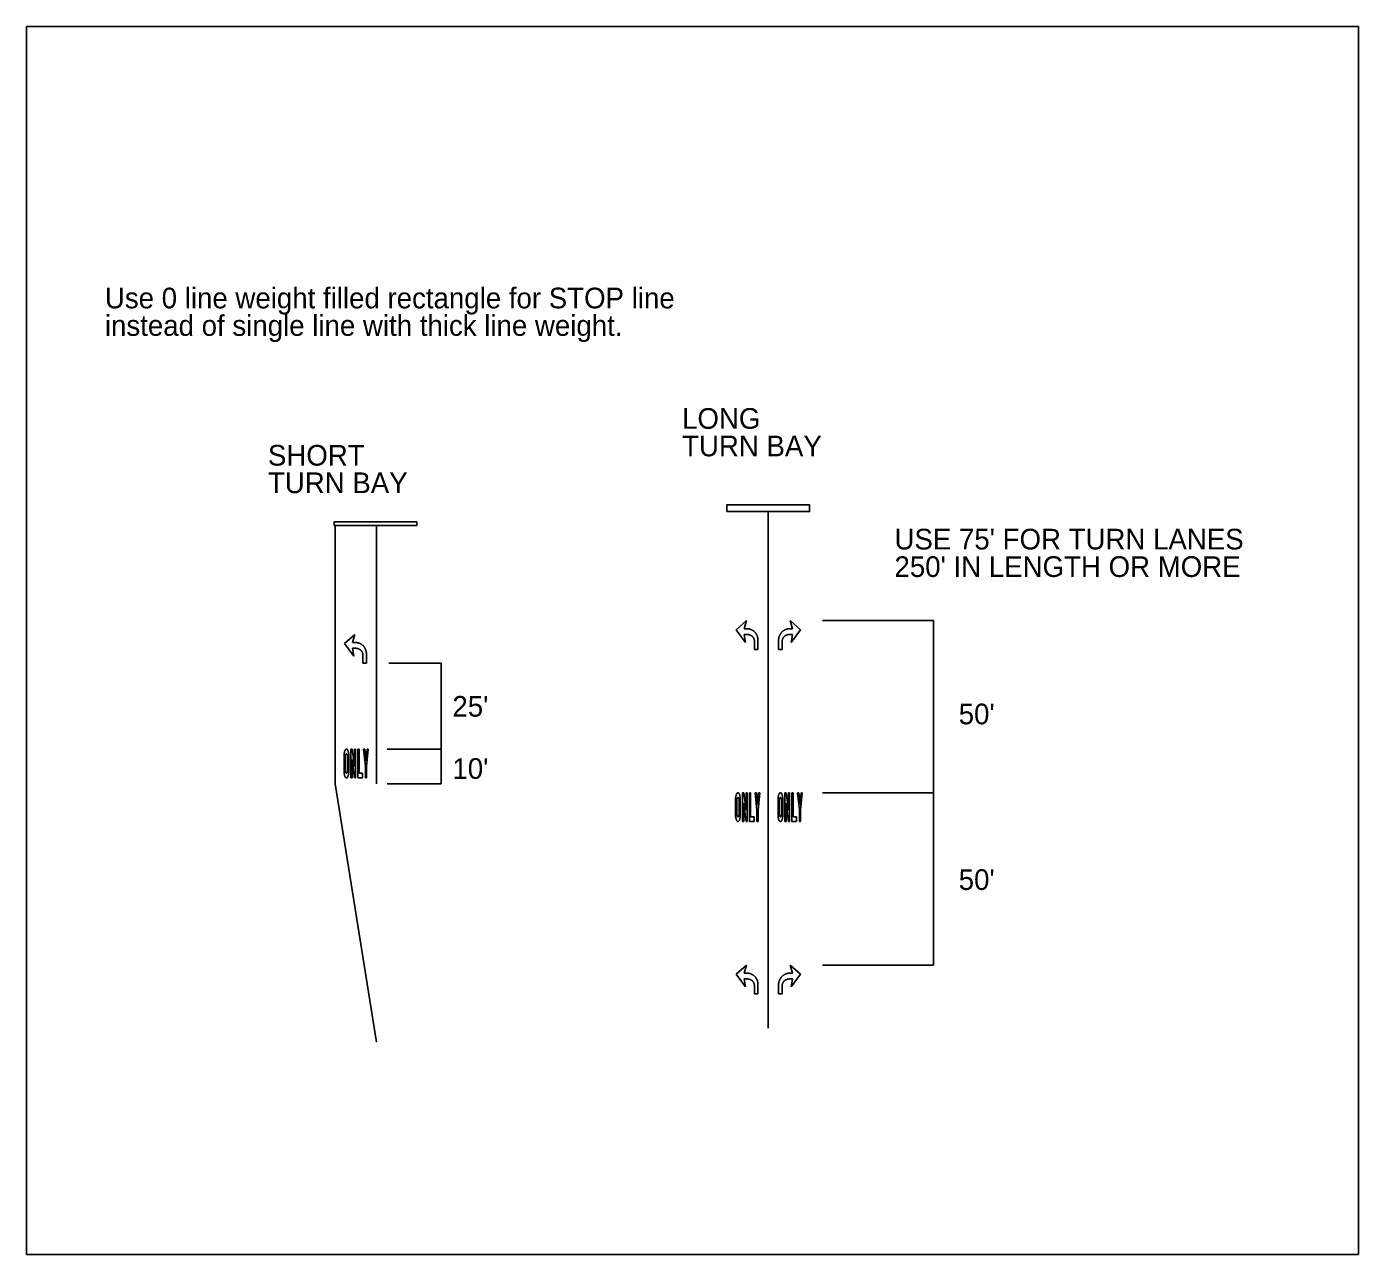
# Model space of a CAD drawing. Extents: x 979036 to 996074, y 1836928 to 1845163.
# Drawn here: x 995687.7 to 996074.4, y 1842782.4 to 1843138.9 of the extents above; entities that cross this region are included whole.
import ezdxf

# ---------------------------------------------------------------- set-up
doc = ezdxf.new("R2010")
doc.units = 0
for name, color, linetype in [('Default', 7, 'Continuous'), ('R_Striping', 7, 'Continuous'), ('STRIPE_White Stopbar', 7, 'Continuous'), ('STRIPE_White Turn Arrow', 7, 'Continuous'), ('STRIPE_White_6in', 7, 'Continuous'), ('STRIPE_White_ONLY', 7, 'Continuous')]:
    doc.layers.add(name, color=color, linetype=linetype)

msp = doc.modelspace()

# ---------------------------------------------------------------- linework, layer by layer
at = {"layer": 'Default'}
for p, q in [((995918.82, 1842966.41), (995951.06, 1842966.41)), ((995951.06, 1842966.41), (995951.06, 1842916.41)), ((995792.86, 1842954.07), (995808.11, 1842954.07)), ((995808.11, 1842954.07), (995808.11, 1842929.07)), ((995792.39, 1842929.07), (995808.11, 1842929.07)), ((995808.11, 1842929.07), (995808.11, 1842919.07)), ((995792.39, 1842919.07), (995808.11, 1842919.07)), ((995918.82, 1842916.41), (995951.06, 1842916.41)), ((995951.06, 1842916.41), (995951.06, 1842866.41)), ((995918.82, 1842866.41), (995951.06, 1842866.41))]:
    msp.add_line(p, q, dxfattribs=at)
msp.add_lwpolyline([(995687.71, 1843138.86), (996074.4, 1843138.86), (996074.4, 1842782.42), (995687.71, 1842782.42)], close=True, dxfattribs=at)
at = {"layer": 'R_Striping'}
for q in [(995777.32, 1842994.07), (995789.32, 1842844.07)]:
    msp.add_line((995777.32, 1842919.07), q, dxfattribs=at)
at = {"layer": 'STRIPE_White Stopbar'}
for points in [[(995891.07, 1842998.07), (995915.07, 1842998.07), (995915.07, 1843000.07), (995891.07, 1843000.07)], [(995776.99, 1842994.07), (995800.99, 1842994.07), (995800.99, 1842995.07), (995776.99, 1842995.07)]]:
    msp.add_lwpolyline(points, close=True, dxfattribs=at)
at = {"layer": 'STRIPE_White Turn Arrow'}
for p, q in [((995896.74, 1842966.41), (995893.74, 1842963.74)), ((995896.06, 1842964.07), (995896.74, 1842966.41)), ((995910.08, 1842964.07), (995909.4, 1842966.41)), ((995909.4, 1842966.41), (995912.4, 1842963.74)), ((995783.04, 1842962.4), (995780.04, 1842959.74)), ((995782.36, 1842960.07), (995783.04, 1842962.4)), ((995893.74, 1842963.74), (995896.4, 1842960.09)), ((995897.06, 1842964.07), (995896.06, 1842964.07)), ((995896.4, 1842960.09), (995896.06, 1842962.39)), ((995896.06, 1842962.39), (995897.07, 1842962.39)), ((995897.07, 1842962.39), (995897.26, 1842962.36)), ((995897.67, 1842963.95), (995897.47, 1842964)), ((995900.07, 1842958.07), (995900.07, 1842961.07)), ((995906.07, 1842958.07), (995906.07, 1842961.07)), ((995908.47, 1842963.95), (995908.67, 1842964)), ((995909.07, 1842962.39), (995908.89, 1842962.36)), ((995910.08, 1842962.39), (995909.07, 1842962.39)), ((995909.08, 1842964.07), (995910.08, 1842964.07)), ((995912.4, 1842963.74), (995909.74, 1842960.09)), ((995909.74, 1842960.09), (995910.08, 1842962.39)), ((995780.04, 1842959.74), (995782.7, 1842956.08)), ((995783.36, 1842960.07), (995782.36, 1842960.07)), ((995782.7, 1842956.08), (995782.36, 1842958.38)), ((995782.36, 1842958.38), (995783.37, 1842958.38)), ((995783.37, 1842958.38), (995783.56, 1842958.35)), ((995783.98, 1842959.95), (995783.77, 1842960)), ((995786.37, 1842954.07), (995786.37, 1842957.07)), ((995899.06, 1842960.38), (995899.07, 1842958.07)), ((995899.07, 1842958.07), (995900.07, 1842958.07)), ((995907.07, 1842958.07), (995906.07, 1842958.07)), ((995907.08, 1842960.38), (995907.07, 1842958.07)), ((995785.36, 1842956.38), (995785.37, 1842954.07)), ((995785.37, 1842954.07), (995786.37, 1842954.07)), ((995896.74, 1842866.41), (995893.74, 1842863.74)), ((995896.06, 1842864.07), (995896.74, 1842866.41)), ((995897.06, 1842864.07), (995896.06, 1842864.07)), ((995897.67, 1842863.95), (995897.47, 1842864)), ((995908.47, 1842863.95), (995908.67, 1842864)), ((995909.08, 1842864.07), (995910.08, 1842864.07)), ((995910.08, 1842864.07), (995909.4, 1842866.41)), ((995909.4, 1842866.41), (995912.4, 1842863.74)), ((995893.74, 1842863.74), (995896.4, 1842860.09)), ((995896.4, 1842860.09), (995896.06, 1842862.39)), ((995896.06, 1842862.39), (995897.07, 1842862.39)), ((995897.07, 1842862.39), (995897.26, 1842862.36)), ((995899.06, 1842860.38), (995899.07, 1842858.07)), ((995900.07, 1842858.07), (995900.07, 1842861.07)), ((995906.07, 1842858.07), (995906.07, 1842861.07)), ((995907.08, 1842860.38), (995907.07, 1842858.07)), ((995909.07, 1842862.39), (995908.89, 1842862.36)), ((995910.08, 1842862.39), (995909.07, 1842862.39)), ((995912.4, 1842863.74), (995909.74, 1842860.09)), ((995909.74, 1842860.09), (995910.08, 1842862.39)), ((995899.07, 1842858.07), (995900.07, 1842858.07)), ((995907.07, 1842858.07), (995906.07, 1842858.07))]:
    msp.add_line(p, q, dxfattribs=at)
for points in [[(995897.47, 1842964), (995897.27, 1842964.05), (995897.06, 1842964.07)], [(995897.26, 1842962.36), (995898.93, 1842962.06), (995899.06, 1842960.38)], [(995900.07, 1842961.07), (995899.66, 1842963.41), (995897.67, 1842963.95)], [(995906.07, 1842961.07), (995906.49, 1842963.41), (995908.47, 1842963.95)], [(995908.89, 1842962.36), (995907.21, 1842962.06), (995907.08, 1842960.38)], [(995908.67, 1842964), (995908.87, 1842964.05), (995909.08, 1842964.07)], [(995783.77, 1842960), (995783.58, 1842960.04), (995783.36, 1842960.07)], [(995783.56, 1842958.35), (995785.23, 1842958.05), (995785.36, 1842956.38)], [(995786.37, 1842957.07), (995785.96, 1842959.41), (995783.98, 1842959.95)], [(995897.47, 1842864), (995897.27, 1842864.05), (995897.06, 1842864.07)], [(995900.07, 1842861.07), (995899.66, 1842863.41), (995897.67, 1842863.95)], [(995906.07, 1842861.07), (995906.49, 1842863.41), (995908.47, 1842863.95)], [(995908.67, 1842864), (995908.87, 1842864.05), (995909.08, 1842864.07)], [(995897.26, 1842862.36), (995898.93, 1842862.06), (995899.06, 1842860.38)], [(995908.89, 1842862.36), (995907.21, 1842862.06), (995907.08, 1842860.38)]]:
    msp.add_open_spline(points, degree=2, dxfattribs=at)
at = {"layer": 'STRIPE_White_6in'}
for p, q in [((995903.07, 1842998.07), (995903.07, 1842848.07)), ((995789.32, 1842994.07), (995789.32, 1842919.07))]:
    msp.add_line(p, q, dxfattribs=at)
at = {"layer": 'STRIPE_White_ONLY'}
for p, q in [((995779.88, 1842927.74), (995779.88, 1842927.75)), ((995779.88, 1842922.09), (995779.88, 1842927.74)), ((995780.22, 1842927.08), (995780.22, 1842922.75)), ((995780.88, 1842922.75), (995780.88, 1842927.08)), ((995781.23, 1842927.76), (995781.23, 1842922.08)), ((995781.89, 1842920.74), (995781.89, 1842929.07)), ((995781.89, 1842929.07), (995782.23, 1842929.07)), ((995782.89, 1842920.74), (995782.21, 1842926.07)), ((995782.21, 1842926.07), (995782.23, 1842920.74)), ((995782.23, 1842929.07), (995782.89, 1842924.07)), ((995782.89, 1842924.07), (995782.89, 1842929.07)), ((995782.89, 1842929.07), (995783.23, 1842929.07)), ((995783.23, 1842929.07), (995783.23, 1842920.74)), ((995783.89, 1842920.74), (995783.89, 1842929.07)), ((995783.89, 1842929.07), (995784.23, 1842929.07)), ((995784.23, 1842929.07), (995784.23, 1842922.08)), ((995785.89, 1842929.07), (995785.56, 1842929.07)), ((995785.56, 1842929.07), (995786.08, 1842924.05)), ((995786.25, 1842925.73), (995785.89, 1842929.07)), ((995786.56, 1842929.07), (995786.25, 1842925.73)), ((995786.41, 1842924.07), (995786.9, 1842929.07)), ((995786.9, 1842929.07), (995786.56, 1842929.07)), ((995784.23, 1842922.08), (995785.22, 1842922.08)), ((995785.22, 1842922.08), (995785.23, 1842920.74)), ((995786.08, 1842924.05), (995786.08, 1842920.74)), ((995786.41, 1842920.74), (995786.41, 1842924.07)), ((995782.23, 1842920.74), (995781.89, 1842920.74)), ((995783.23, 1842920.74), (995782.89, 1842920.74)), ((995785.23, 1842920.74), (995783.89, 1842920.74)), ((995786.08, 1842920.74), (995786.41, 1842920.74)), ((995893.58, 1842915.08), (995893.58, 1842915.09)), ((995893.58, 1842909.42), (995893.58, 1842915.08)), ((995893.92, 1842914.42), (995893.92, 1842910.09)), ((995894.58, 1842910.09), (995894.58, 1842914.42)), ((995894.92, 1842915.09), (995894.92, 1842909.42)), ((995895.59, 1842908.07), (995895.59, 1842916.41)), ((995895.59, 1842916.41), (995895.92, 1842916.41)), ((995895.92, 1842916.41), (995896.59, 1842911.41)), ((995896.59, 1842911.41), (995896.59, 1842916.41)), ((995896.59, 1842916.41), (995896.92, 1842916.41)), ((995896.92, 1842916.41), (995896.92, 1842908.07)), ((995897.59, 1842908.07), (995897.59, 1842916.41)), ((995897.59, 1842916.41), (995897.92, 1842916.41)), ((995897.92, 1842916.41), (995897.93, 1842909.41)), ((995899.59, 1842916.41), (995899.26, 1842916.41)), ((995899.26, 1842916.41), (995899.78, 1842911.39)), ((995899.94, 1842913.07), (995899.59, 1842916.41)), ((995900.26, 1842916.41), (995899.94, 1842913.07)), ((995900.11, 1842911.4), (995900.59, 1842916.41)), ((995900.59, 1842916.41), (995900.26, 1842916.41)), ((995905.9, 1842915.08), (995905.9, 1842915.09)), ((995905.9, 1842909.42), (995905.9, 1842915.08)), ((995906.24, 1842914.42), (995906.24, 1842910.09)), ((995906.9, 1842910.09), (995906.9, 1842914.42)), ((995907.25, 1842915.09), (995907.25, 1842909.42)), ((995907.91, 1842908.07), (995907.91, 1842916.41)), ((995907.91, 1842916.41), (995908.25, 1842916.41)), ((995908.25, 1842916.41), (995908.91, 1842911.41)), ((995908.91, 1842911.41), (995908.91, 1842916.41)), ((995908.91, 1842916.41), (995909.25, 1842916.41)), ((995909.25, 1842916.41), (995909.25, 1842908.07)), ((995909.91, 1842908.07), (995909.91, 1842916.41)), ((995909.91, 1842916.41), (995910.25, 1842916.41)), ((995910.25, 1842916.41), (995910.25, 1842909.41)), ((995911.92, 1842916.41), (995911.58, 1842916.41)), ((995911.58, 1842916.41), (995912.1, 1842911.39)), ((995912.27, 1842913.07), (995911.92, 1842916.41)), ((995912.58, 1842916.41), (995912.27, 1842913.07)), ((995912.43, 1842911.4), (995912.92, 1842916.41)), ((995912.92, 1842916.41), (995912.58, 1842916.41)), ((995896.59, 1842908.07), (995895.9, 1842913.41)), ((995895.9, 1842913.41), (995895.92, 1842908.07)), ((995899.78, 1842911.39), (995899.78, 1842908.07)), ((995900.11, 1842908.07), (995900.11, 1842911.4)), ((995908.91, 1842908.07), (995908.23, 1842913.41)), ((995908.23, 1842913.41), (995908.25, 1842908.07)), ((995912.1, 1842911.39), (995912.1, 1842908.07)), ((995912.43, 1842908.07), (995912.43, 1842911.4)), ((995895.92, 1842908.07), (995895.59, 1842908.07)), ((995896.92, 1842908.07), (995896.59, 1842908.07)), ((995898.92, 1842908.07), (995897.59, 1842908.07)), ((995897.93, 1842909.41), (995898.92, 1842909.41)), ((995898.92, 1842909.41), (995898.92, 1842908.07)), ((995899.78, 1842908.07), (995900.11, 1842908.07)), ((995908.25, 1842908.07), (995907.91, 1842908.07)), ((995909.25, 1842908.07), (995908.91, 1842908.07)), ((995911.25, 1842908.07), (995909.91, 1842908.07)), ((995910.25, 1842909.41), (995911.25, 1842909.41)), ((995911.25, 1842909.41), (995911.25, 1842908.07)), ((995912.1, 1842908.07), (995912.43, 1842908.07))]:
    msp.add_line(p, q, dxfattribs=at)
for centre, start, end in [((995780.56, 1842928.85), 62.2844, 117.7155), ((995780.56, 1842920.98), 242.2844, 306.378), ((995894.26, 1842916.19), 62.2844, 117.7155), ((995906.58, 1842916.19), 62.2844, 117.7155), ((995894.26, 1842908.32), 242.2844, 306.378), ((995906.58, 1842908.32), 242.2844, 306.378)]:
    msp.add_arc(centre, 0.261, start, end, dxfattribs=at)
for points in [[(995779.88, 1842927.75), (995780.1, 1842928.9), (995780.44, 1842929.08)], [(995780.55, 1842927.76), (995780.38, 1842927.74), (995780.22, 1842927.08)], [(995780.88, 1842927.08), (995780.73, 1842927.74), (995780.55, 1842927.76)], [(995780.68, 1842929.08), (995781.02, 1842928.9), (995781.23, 1842927.76)], [(995780.44, 1842920.75), (995780.1, 1842920.94), (995779.88, 1842922.09)], [(995780.22, 1842922.75), (995780.38, 1842922.1), (995780.55, 1842922.08)], [(995780.55, 1842922.08), (995780.72, 1842922.09), (995780.88, 1842922.75)], [(995781.23, 1842922.08), (995781.03, 1842920.99), (995780.72, 1842920.77)], [(995893.58, 1842915.09), (995893.8, 1842916.24), (995894.14, 1842916.42)], [(995894.25, 1842915.09), (995894.08, 1842915.08), (995893.92, 1842914.42)], [(995894.58, 1842914.42), (995894.42, 1842915.08), (995894.25, 1842915.09)], [(995894.38, 1842916.42), (995894.72, 1842916.24), (995894.92, 1842915.09)], [(995905.9, 1842915.09), (995906.12, 1842916.24), (995906.46, 1842916.42)], [(995906.57, 1842915.09), (995906.4, 1842915.08), (995906.24, 1842914.42)], [(995906.9, 1842914.42), (995906.75, 1842915.08), (995906.57, 1842915.09)], [(995906.7, 1842916.42), (995907.04, 1842916.24), (995907.25, 1842915.09)], [(995894.14, 1842908.09), (995893.8, 1842908.27), (995893.58, 1842909.42)], [(995893.92, 1842910.09), (995894.08, 1842909.43), (995894.25, 1842909.42)], [(995894.25, 1842909.42), (995894.42, 1842909.43), (995894.58, 1842910.09)], [(995894.92, 1842909.42), (995894.73, 1842908.33), (995894.41, 1842908.11)], [(995906.46, 1842908.09), (995906.12, 1842908.27), (995905.9, 1842909.42)], [(995906.24, 1842910.09), (995906.4, 1842909.43), (995906.57, 1842909.42)], [(995906.57, 1842909.42), (995906.75, 1842909.43), (995906.9, 1842910.09)], [(995907.25, 1842909.42), (995907.05, 1842908.33), (995906.74, 1842908.11)]]:
    msp.add_open_spline(points, degree=2, dxfattribs=at)

# ---------------------------------------------------------------- texts
at = {"layer": 'Default'}
for s, p in [('Use 0 line weight filled rectangle for STOP line', (995710.43, 1843057.07)), ('instead of single line with thick line weight.', (995710.43, 1843049.09)), ('LONG', (995878.03, 1843022.1)), ('TURN BAY', (995878.03, 1843014.12)), ('SHORT', (995757.77, 1843011.42)), ('TURN BAY', (995757.77, 1843003.43)), ("USE 75' FOR TURN LANES", (995939.7, 1842987.07)), ("250' IN LENGTH OR MORE", (995939.7, 1842979.09)), ("25'", (995811.34, 1842938.53)), ("50'", (995958.35, 1842936.31)), ("10'", (995811.34, 1842920.47)), ("50'", (995958.35, 1842888.22))]:
    msp.add_text(s, height=6, dxfattribs=at).set_placement(p)

doc.saveas('drawing.dxf')
